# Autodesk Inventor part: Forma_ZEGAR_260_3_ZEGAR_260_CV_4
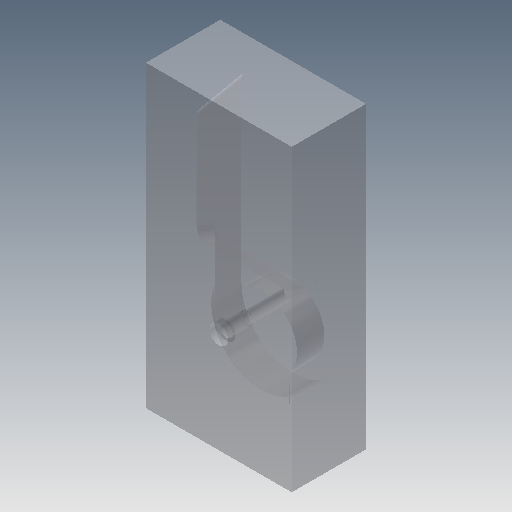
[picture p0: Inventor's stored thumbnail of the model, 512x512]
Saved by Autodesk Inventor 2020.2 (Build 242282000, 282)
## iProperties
Created: 2015-01
Part Number: Forma_ZEGAR_260_3_ZEGAR_260_CV_4
Material: Ogólny
Document SubType Name: Modeling
Designer: F.Stasiak
Density: 1 g/cm^3
Appearance: Domyślna
Catalog Web Link: www.expertbooks.pl
Manager: www.cadconsulting.pl
Company: Fabian Stasiak CAD Consulting
Author: F.Stasiak
Subject: Zbiór ćwiczeń. Autodesk Inventor 2020. Kurs Professional
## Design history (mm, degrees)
node "Forma_ZEGAR_260_3_ZEGAR_260_CV_Base"
feature "Rzeźbienie3"
feature "Bryła1::Forma_ZEGAR_260_3_ZEGAR_260_CV_Base"
tag "Bryła wyprowadzona1"
node "Bryła1"
feature "Forma_ZEGAR_260_3_ZEGAR_260_CV_Base_Bodies"
feature "Powierzchnia3"
body "Srf3"
